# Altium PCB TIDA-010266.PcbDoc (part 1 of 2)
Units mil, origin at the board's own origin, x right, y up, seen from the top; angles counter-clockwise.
Board outline 2450.67 x 2507.13 mil, 4 copper layers (Top Layer, Signal Layer 1, Signal Layer 2, Bottom Layer), stack 61.6 mil thick; 88 components, 56 nets, 233 pads, 159 vias.
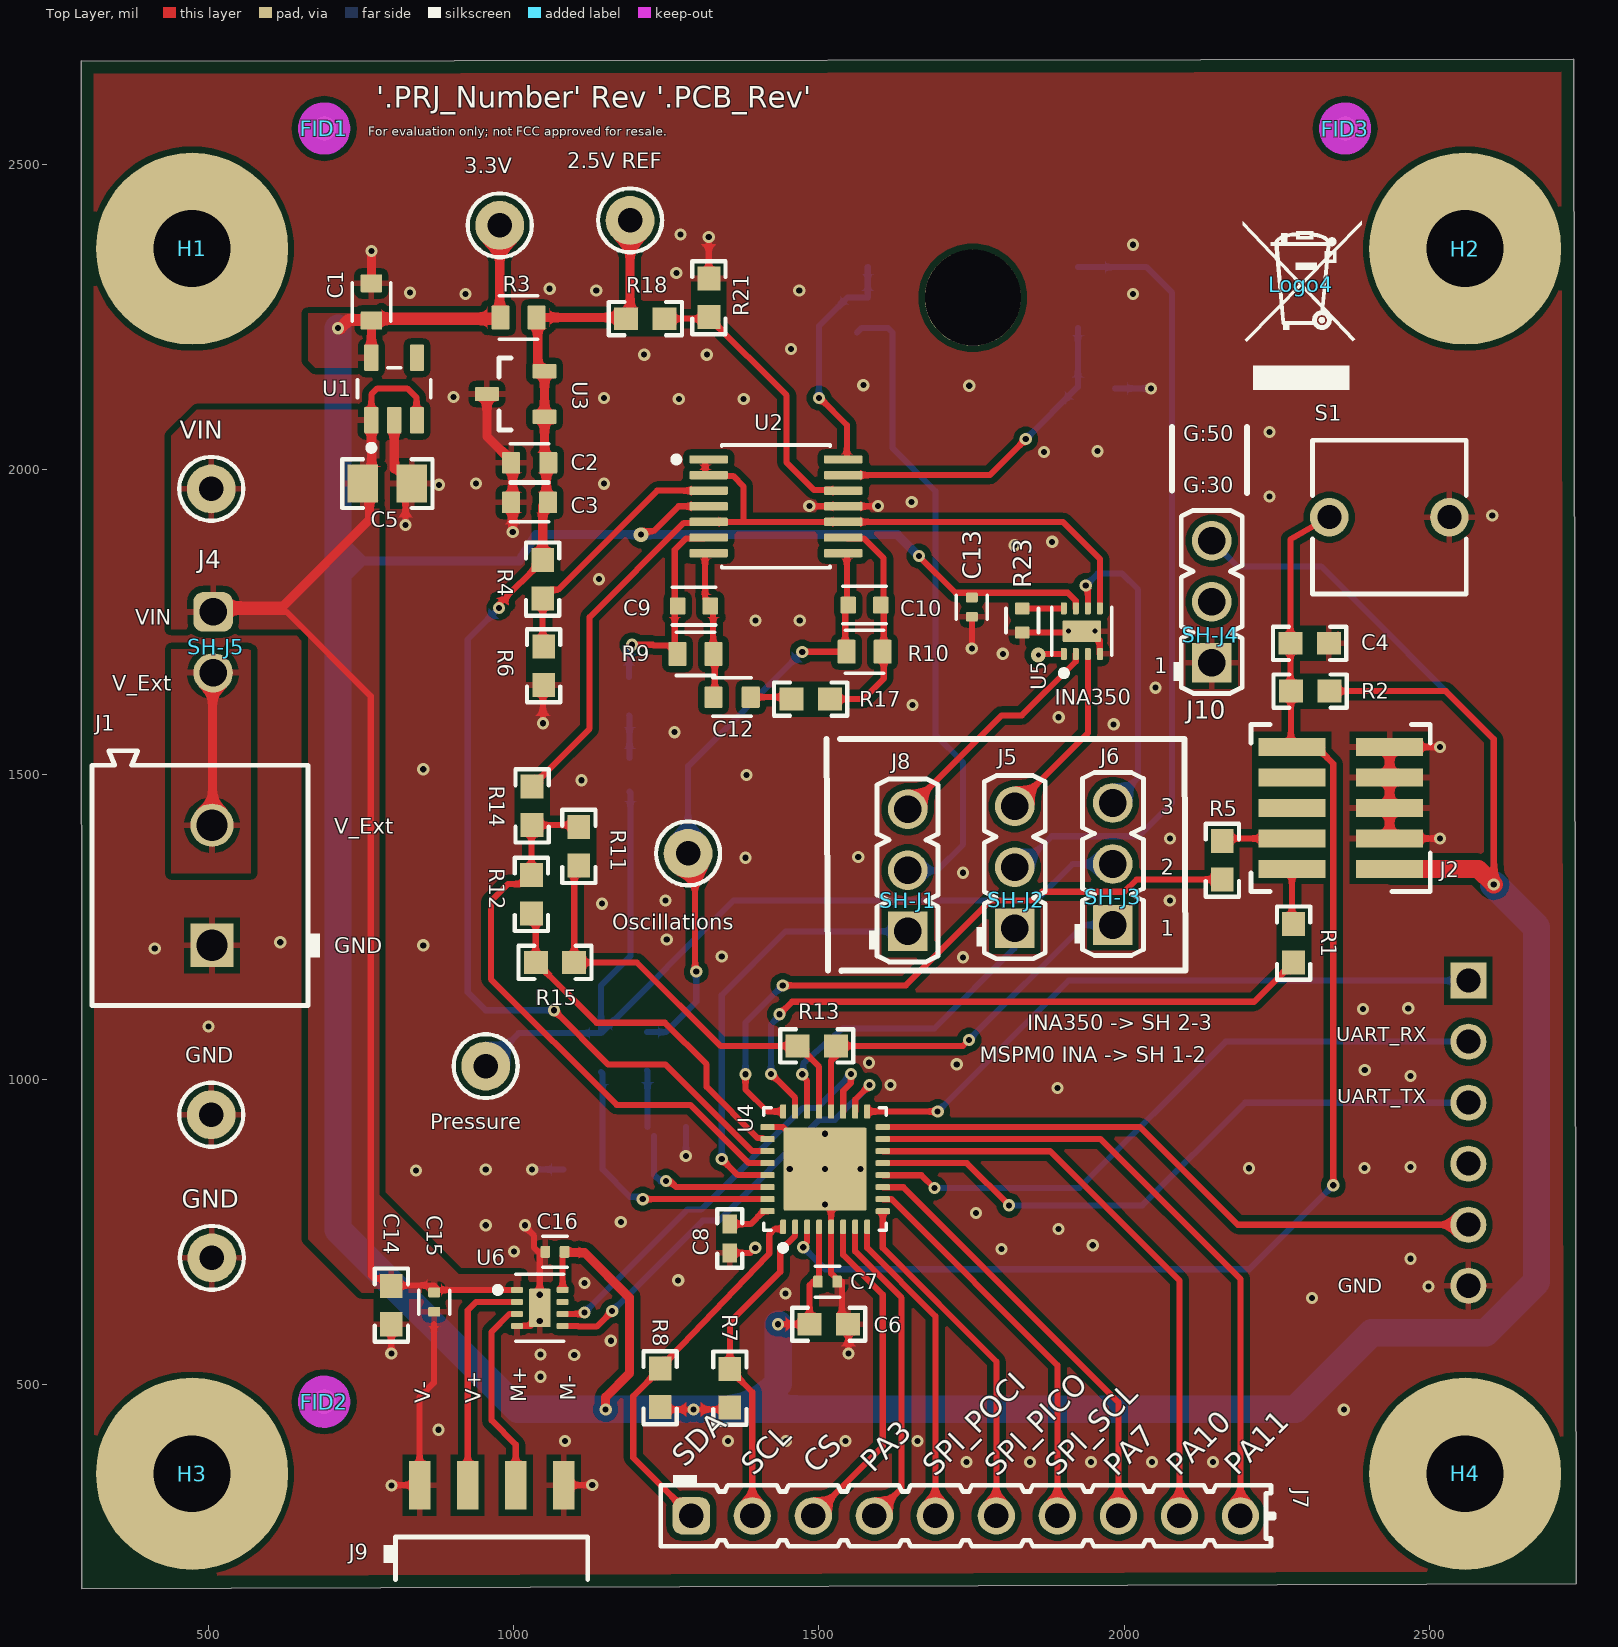
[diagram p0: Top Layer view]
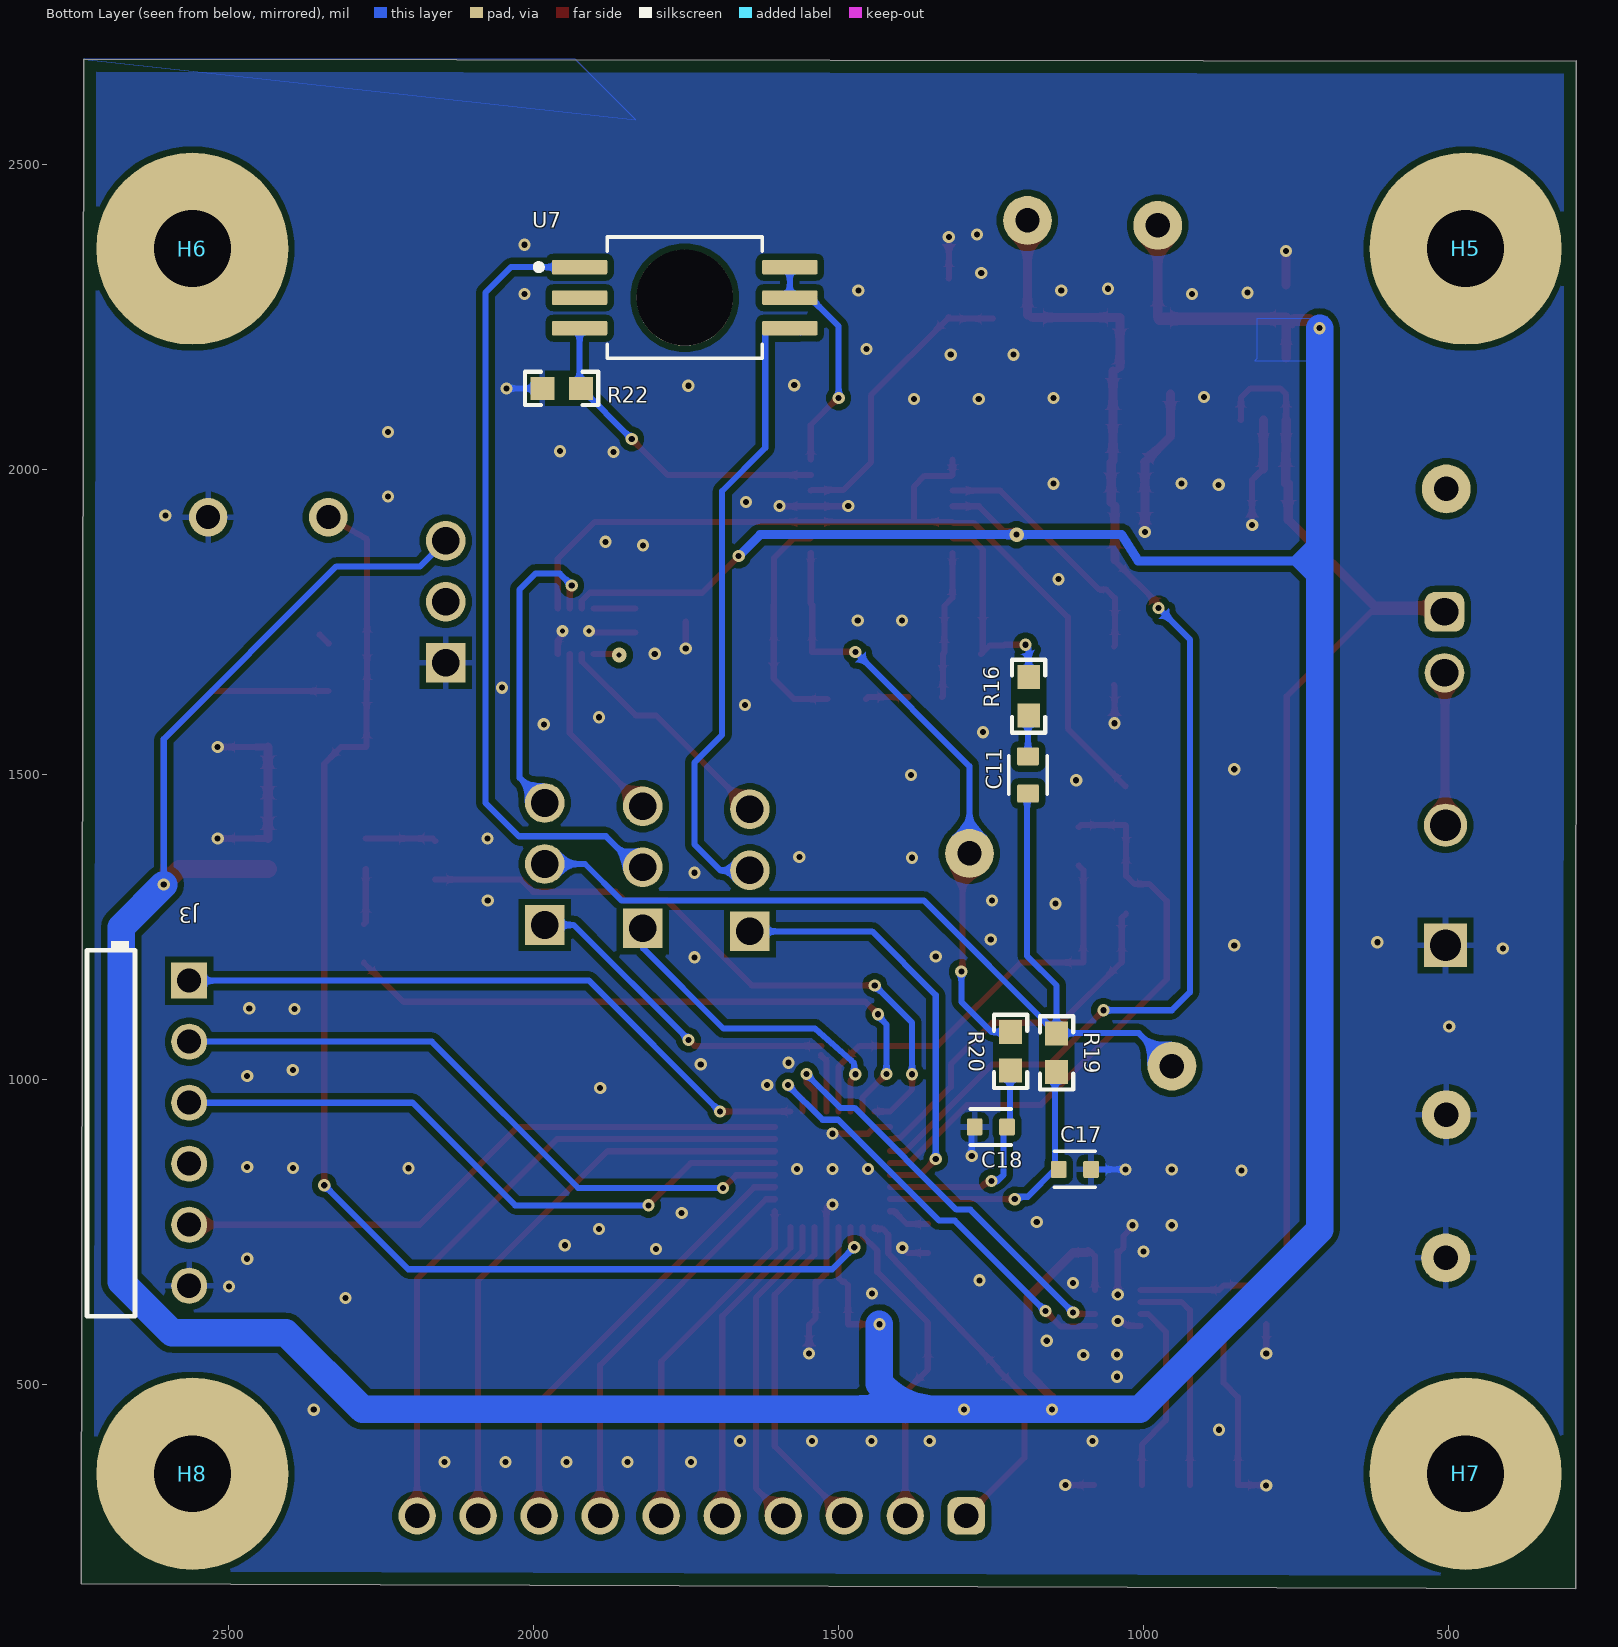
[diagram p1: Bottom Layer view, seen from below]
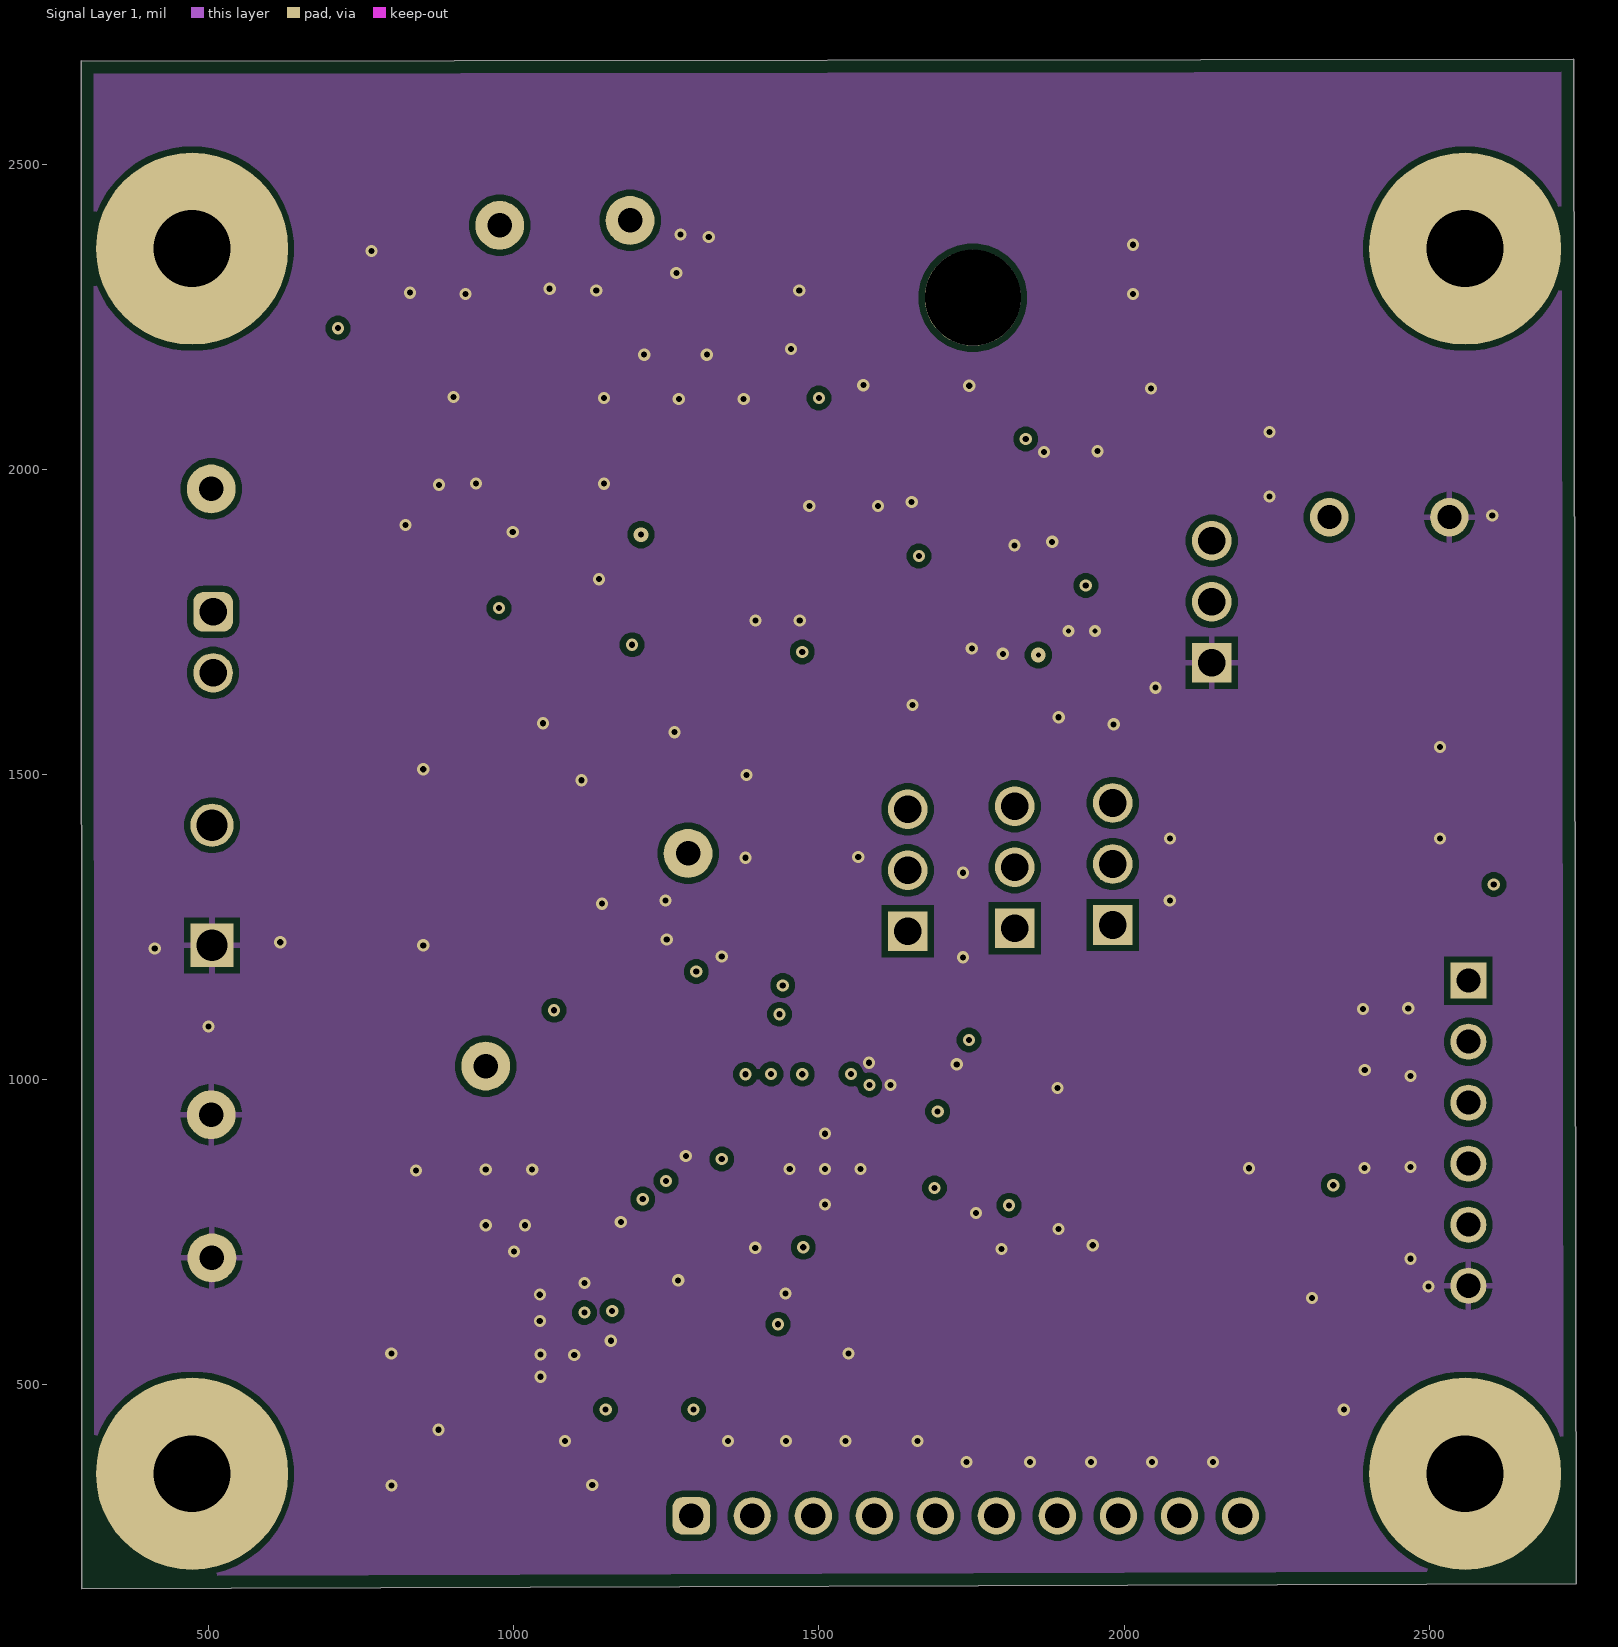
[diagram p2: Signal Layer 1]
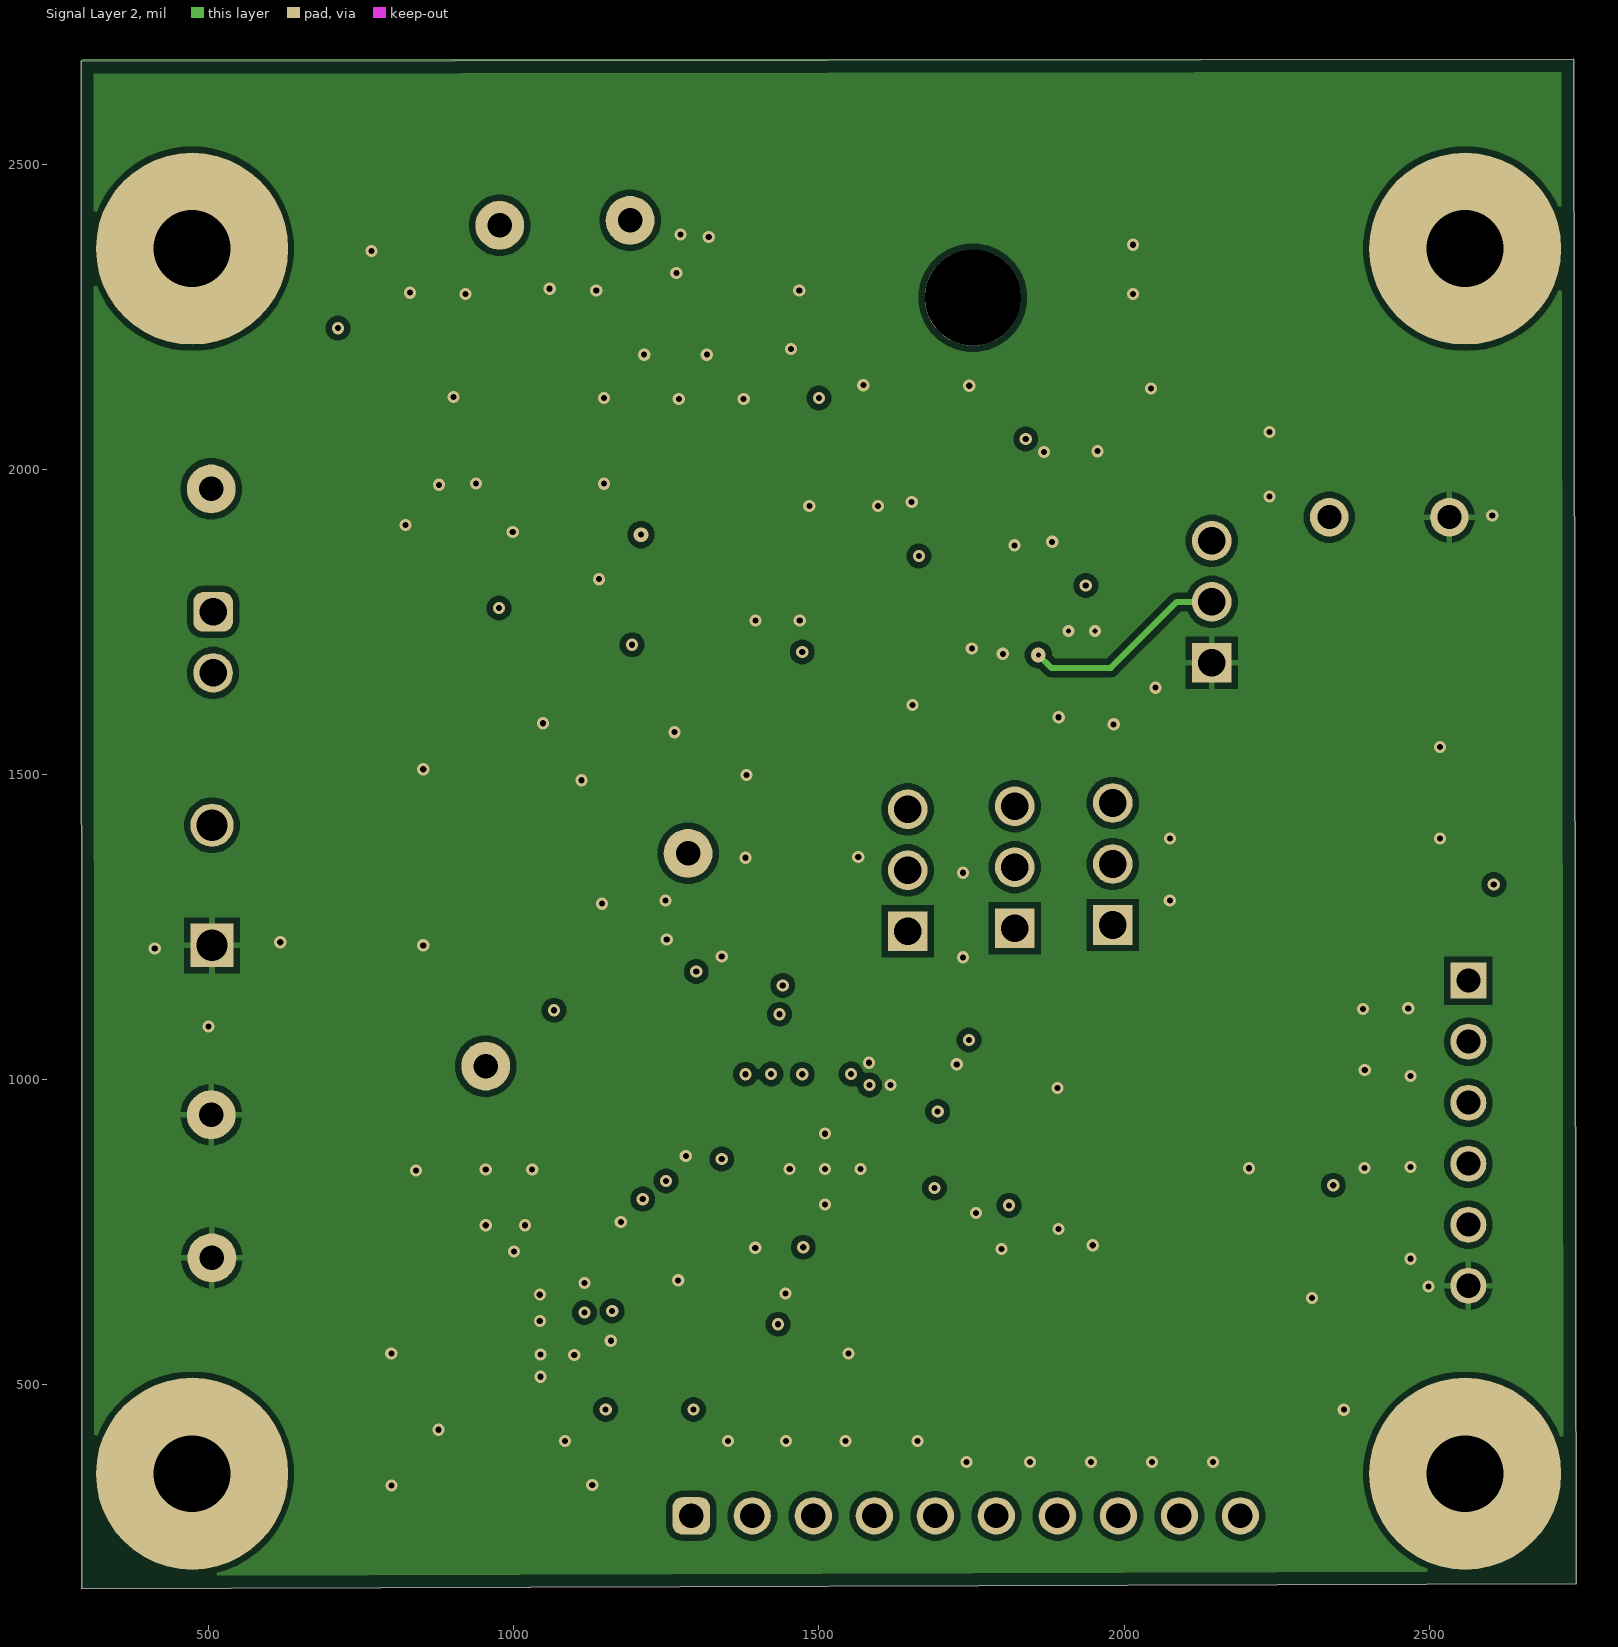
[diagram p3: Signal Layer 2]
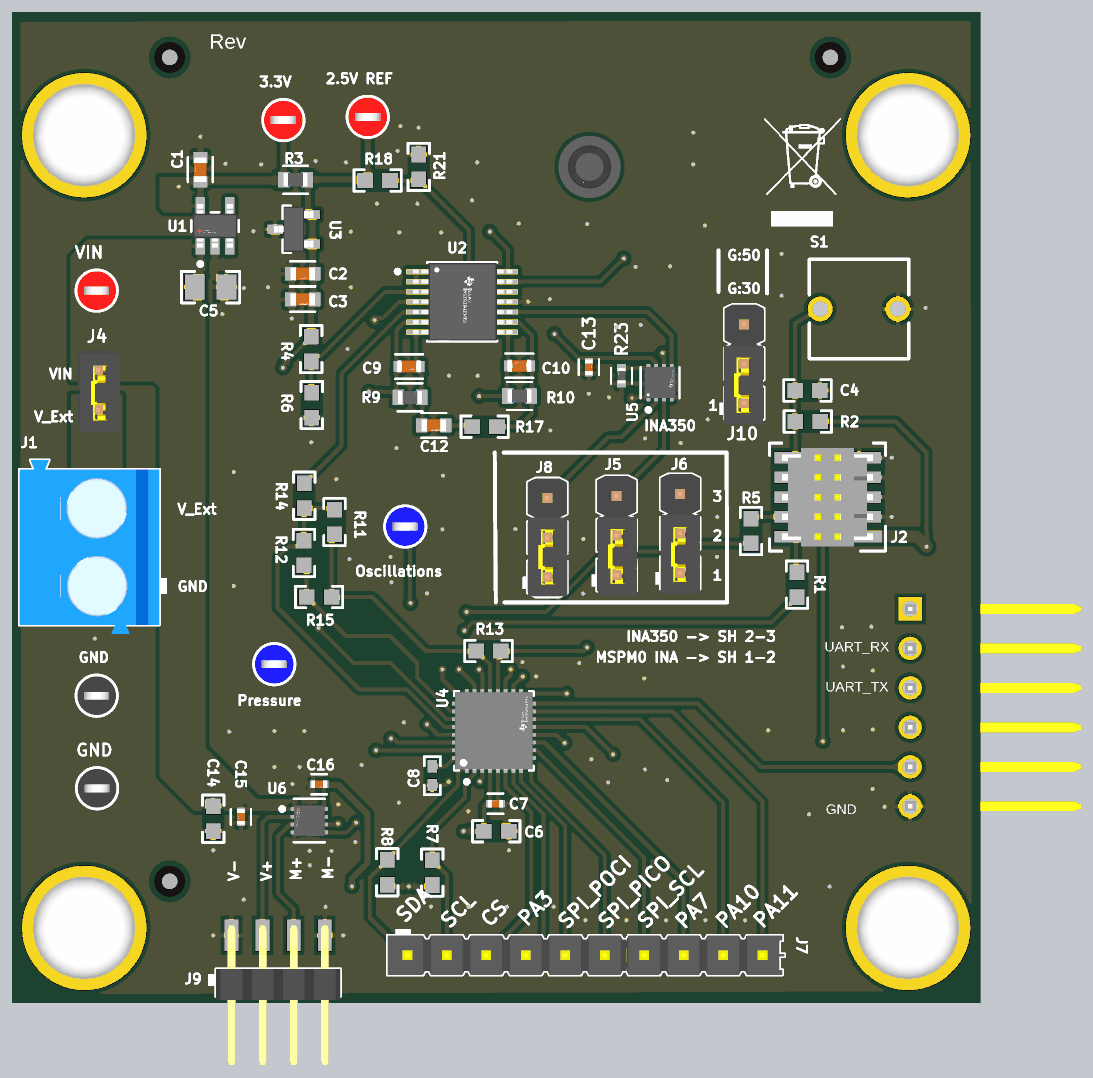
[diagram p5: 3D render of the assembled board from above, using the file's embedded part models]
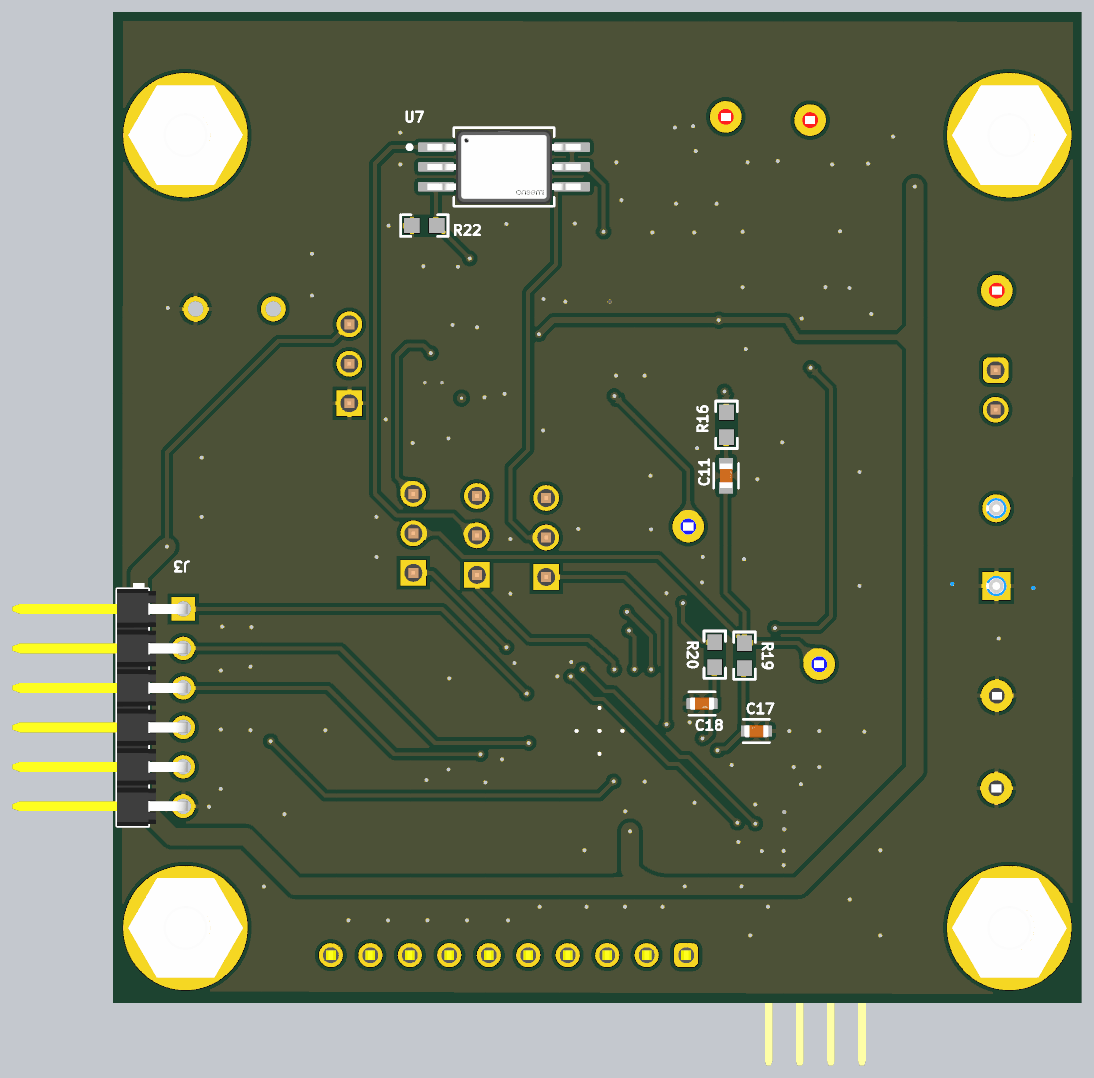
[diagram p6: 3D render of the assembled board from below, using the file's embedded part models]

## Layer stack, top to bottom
Top Solder: solder mask 0.4, Solder Resist, Dk 3.5
Top Layer: signal copper 1.4
Dielectric 1: prepreg 8, FR-4 High Tg, Dk 4.2
Signal Layer 1: signal copper 1.4
Dielectric 2: core 40, FR-4 High Tg, Dk 4.2
Signal Layer 2: signal copper 1.4
Dielectric 3: prepreg 8, FR-4 High Tg, Dk 4.2
Bottom Layer: signal copper 1.4
Bottom Solder: solder mask 0.4, Solder Resist, Dk 3.5

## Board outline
291.81,165.64 291.07,2669.88 290.71,2669.49 2737.21,2672.77 2736.86,2672.31 2741.38,173.75 2740.98,174.04

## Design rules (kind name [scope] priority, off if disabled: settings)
AcuteAngle [All] p1: minimum=4.50000000000000E+0001 checktracksonly=FALSE
AssemblyTestPointUsage [All] p1: valid=2
BoardOutlineClearance BoardOutlineClearance_MountingHoles [OnCopper and InComponentClass('Mounting Holes')] p1: gap=20 ignorepadtopadclearanceinfootprint=FALSE
BoardOutlineClearance BoardOutlineClearance_Poly [OnCopper and IsPoly] p2: gap=20 ignorepadtopadclearanceinfootprint=FALSE
BoardOutlineClearance [OnCopper and Not InComponentClass('Logo') and not InComponentClass('FiducialMark') and not InRegion(1000,500,4000,800) and not InPoly] p3: gap=20 ignorepadtopadclearanceinfootprint=FALSE
Clearance Clearance_Keepouts [((IsTrack Or IsArc) And Not InPoly) And IsFree and IsKeepOut vs ((IsTrack Or IsArc) And Not InPoly) And IsFree and IsKeepOut] p1: gap=0 ignorepadtopadclearanceinfootprint=FALSE
Clearance Clearance_Poly [InPolygon] p2: gap=10 ignorepadtopadclearanceinfootprint=TRUE
Clearance Clearance_FiducialMark [IsKeepOut and InComponentClass('FiducialMark') vs IsPad and InComponentClass('FiducialMark')] p3: gap=0 ignorepadtopadclearanceinfootprint=FALSE
Clearance [All] p4: gap=8 ignorepadtopadclearanceinfootprint=TRUE
ComponentClearance ComponentClearance_MountingHoles_FiducialMarks [InComponentClass('Mounting Holes') vs InComponentClass('FiducialMark')] p1: gap=10 collisioncheckmode=3 verticalgap=10 showdistances=FALSE
ComponentClearance ComponentClearance_Shunt [InComponentClass('Header') vs InComponentClass('Shunt')] p2: gap=0 collisioncheckmode=3 verticalgap=0 showdistances=FALSE
ComponentClearance ComponentClearance_Logo [InComponentClass('Logo')] p3: gap=10 collisioncheckmode=3 verticalgap=10 showdistances=FALSE
ComponentClearance ComponentClearance_ScrewToNut [(HasFootprint('NY PMS 440 0025 PH')) vs (HasFootprint('Keystone_1902C'))] p4: gap=5 collisioncheckmode=3 verticalgap=10 showdistances=FALSE
ComponentClearance ComponentClearance_MountingHoles [InComponentClass('Mounting Holes')] p5: gap=10 collisioncheckmode=3 verticalgap=100000 showdistances=FALSE
ComponentClearance ComponentClearance_SmallPassives [HasFootprint('0201*') or HasFootprint('0402*') or HasFootprint('0508') or HasFootprint('0603*') or HasFootprint('0612') or HasFootprint('0805*') or HasFootprint('0815*') or HasFootprint('0830*') or HasFootprint('1206*') or HasFootprint('1210*') or HasFootprint('1808*') or HasFootprint('1812*') or HasFootprint('1825*') or HasFootprint('2010*') or HasFootprint('2220*') or HasFootprint('2225*') or HasFootprint('2512*') or HasFootprint('2728*') or HasFootprint('3518*') vs HasFootprint('0201*') or HasFootprint('0402*') or HasFootprint('0508') or HasFootprint('0603*') or HasFootprint('0612') or HasFootprint('0805*') or HasFootprint('0815*') or HasFootprint('0830*') or HasFootprint('1206*') or HasFootprint('1210*') or HasFootprint('1808*') or HasFootprint('1812*') or HasFootprint('1825*') or HasFootprint('2010*') or HasFootprint('2220*') or HasFootprint('2225*') or HasFootprint('2512*') or HasFootprint('2728*') or HasFootprint('3518*')] p6: gap=10 collisioncheckmode=3 verticalgap=10 showdistances=FALSE
ComponentClearance ComponentClearance_THtoSMT [IsThruComponent vs IsSMTComponent] p7: gap=10 collisioncheckmode=3 verticalgap=30 showdistances=FALSE
ComponentClearance ComponentClearance_THtoTH [IsThruComponent vs IsThruComponent] p8: gap=10 collisioncheckmode=3 verticalgap=30 showdistances=FALSE
ComponentClearance [All] p9: gap=10 collisioncheckmode=3 verticalgap=10 showdistances=FALSE
DiffPairsRouting [All] p1: maxlimit=100 minlimit=10 mostfreqgap=10 toplayer_minwidth=15 toplayer_maxwidth=15 toplayer_prefwidth=15 midlayer1_minwidth=15 midlayer1_maxwidth=15 midlayer1_prefwidth=15 midlayer2_minwidth=15 midlayer2_maxwidth=15 midlayer2_prefwidth=15 bottomlayer_minwidth=15 bottomlayer_maxwidth=15 bottomlayer_prefwidth=15 maxuncoupledlength=1000
FabricationTestPointUsage TestPointUsage [All] p1: valid=2 allowmultiple=FALSE
FabricationTestpoint Testpoint [All] p1: side=3 testpointundercomponent=TRUE minsize=40 maxsize=100 preferedsize=60 minholesize=0 maxholesize=40 preferedholesize=32 testpointgrid=1 allowsidetop=TRUE allowsidebottom=TRUE usegrid=TRUE gridtolerance=0.01
FanoutControl Fanout_LCC [IsLCC] p1: bgadir=Out bgaviamode=Centered fanoutstyle=Auto fanoutdirection=Alternating viagrid=1 // Fanout_LCC (Default Rule)
FanoutControl Fanout_BGA [IsBGA] p2: bgadir=Out bgaviamode=Centered fanoutstyle=Auto fanoutdirection=Alternating viagrid=1 // Fanout_BGA (Default Rule)
FanoutControl Fanout_Default [All] p4: bgadir=Out bgaviamode=Centered fanoutstyle=Auto fanoutdirection=Alternating viagrid=1 // Fanout_Default (Default Rule)
FanoutControl Fanout_Small [(CompPinCount < 5)] p5: bgadir=Out bgaviamode=Centered fanoutstyle=Auto fanoutdirection=OutThenIn viagrid=1 // Fanout_Small (Default Rule)
HoleSize [All] p1: absolutevalues=TRUE maxlimit=251 minlimit=6 maxpercent=80.000 minpercent=20.000
MinimumAnnularRing MinimumAnnularRing_ThermalPadVias [IsVia and InAnyComponent] p1: minimumring=5.91
MinimumAnnularRing [All] p2: minimumring=7.87
MinimumSolderMaskSliver MinimumSolderMaskSliver_Logo [InComponentClass('Logo') vs InComponentClass('Logo')] p1: minsoldermaskwidth=0.7
MinimumSolderMaskSliver [All] p2: minsoldermaskwidth=3.94
PlaneConnect [All] p1: planeconnectstyle=Relief reliefexpansion=10 reliefentries=4 reliefconductorwidth=10 reliefairgap=10
PolygonConnect [All] p1: thpad.connectstyle=Relief thpad.reliefconductorwidth=10 thpad.reliefentries=4 thpad.polygonreliefangle="90 Angle" thpad.airgapwidth=10 smdpad.connectstyle=Relief smdpad.reliefconductorwidth=10 smdpad.reliefentries=4 smdpad.polygonreliefangle="90 Angle" smdpad.airgapwidth=10 via.connectstyle=Direct via.reliefconductorwidth=10 via.reliefentries=4 via.polygonreliefangle="90 Angle" via.airgapwidth=10
RoutingLayers [All] p1: top layer_v5=TRUE mid layer 1_v5=FALSE mid layer 2_v5=FALSE bottom layer_v5=TRUE
RoutingVias ThermalPadVias [IsVia and InAnyComponent] p1: holewidth=7.87 width=19.68 viastyle="Through Hole" minholewidth=7.87 minwidth=19.68 maxholewidth=12.99 maxwidth=23.62
RoutingVias [All] p2: holewidth=10 width=10 viastyle="Through Hole" minholewidth=7.87 minwidth=20 maxholewidth=40 maxwidth=65
SilkToBoardRegionClearance [Not ((IsComment or IsDesignator) And (Hide <> 'False')) and not InRegion(1000,500,4000,800)] p1:
SilkToSilkClearance SilkToSilkClearance_Pb-FreeLogo [(HasFootprint('Pb-Free_Overlay_Medium') OR HasFootprint('Pb-Free_Overlay_Small')) vs (HasFootprint('Pb-Free_Overlay_Medium') OR HasFootprint('Pb-Free_Overlay_Small'))] p1: silktosilkclearance=0
SilkToSilkClearance [All] p2: silktosilkclearance=3.94
SilkToSolderMaskClearance SilkToComponentPadClearance [(IsPad or IsFill or IsRegion) and InAnycomponent] p1: minsilkscreentomaskgap=5 clearancetoexposedcopper=TRUE
SilkToSolderMaskClearance "Silk to Solder Mask Opening" [All] p2: minsilkscreentomaskgap=3.94 clearancetoexposedcopper=FALSE
SolderMaskExpansion [All] p1: expansion=1.97 istentingtop=FALSE
UnRoutedNet [All] p1: checkbadconnections=TRUE
Width [All] p1: maxlimit=100 minlimit=6 preferedwidth=10 checkconnectedcopper=TRUE
13 further rules are at their usual default settings.

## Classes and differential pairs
component class Shunt: SH-J1 SH-J2 SH-J3 SH-J4 SH-J5
component class TIDA-010266_BPM: C1 C2 C3 C4 C5 C6 C7 C8 C9 C10 C11 C12 C13 C14 C15 C16 C17 C18 J1 J2 J3 J4 J5 J6 J7 J8 J9 J10 R1 R2 R3 R4 R5 R6 R7 R8 R9 R10 R11 R12 R13 R14 R15 R16 R17 R18 R19 R20 R21 R22 R23 S1 TP1 TP2 TP3 TP4 TP5 TP6 U1 U2 U3 U4 U5 U6 U7
component class Header: J3 J4 J5 J6 J7 J8 J9 J10
component class AssemblyNote: ZZ1 ZZ2 ZZ3 ZZ4
component class FiducialMark: FID1 FID2 FID3
component class TIDA-010266_Hardware: FID1 FID2 FID3 H1 H2 H3 H4 H5 H6 H7 H8 Logo3 Logo4 SH-J1 SH-J2 SH-J3 SH-J4 SH-J5 ZZ1 ZZ2 ZZ3 ZZ4
component class "Mounting Holes": H1 H2 H3 H4

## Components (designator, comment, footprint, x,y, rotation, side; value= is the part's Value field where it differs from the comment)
"2.5V REF" "5000" Keystone5000 1190.4,2408.56 r90 top (schematic designator TP4)
3.3V "5000" Keystone5000 976.76,2400.4 r90 top (schematic designator TP3)
C1 "GRM188R61C475KE11D" FP-GRM188R61C475KE11D_0603-MFG 766.49,2274.82 r270 top value=4.7µF
C2 "GRM188R61C475KE11D" FP-GRM188R61C475KE11D_0603-MFG 1025.89,2011.23 r0 top value=4.7µF
C3 "GRM188R61C475KE11D" FP-GRM188R61C475KE11D_0603-MFG 1025.59,1946.25 r0 top value=4.7µF
C4 "GRM1885C1H112JA01D" 0603 2304.16,1715.31 r0 top value=1100pF
C5 "GCM21BR71H105KA03K" 0805_HV 792.58,1977.24 r0 top value=1uF
C6 "GRM188R61A106ME69D" 0603 1516.04,599.3 r0 top value=10uF
C7 "GRM155R71E104KE14J" FP-GRM155R71E104KE14J_0402-MFG 1513.95,669.03 r180 top value=100nF
C8 "GRM155C80J474KE19D" 0402 1353.83,739.94 r270 top value=0.47uF
C9 "GCJ188R71E104KA12D" FP-GCJ188R71E104KA12D_0603-MFG 1295.12,1776.5 r0 top value=100nF
C10 "GCJ188R71E104KA12D" FP-GCJ188R71E104KA12D_0603-MFG 1574.55,1777.91 r180 top value=100nF
C11 "GRM188R61C475KE11D" FP-GRM188R61C475KE11D_0603-MFG 1189.5,1499.58 r90 bottom value=4.7µF
C12 "GRM188R61C475KE11D" FP-GRM188R61C475KE11D_0603-MFG 1357.67,1627.1 r0 top value=4.7µF
C13 "GRM155R71E104KE14J" FP-GRM155R71E104KE14J_0402-MFG 1750.51,1774.65 r90 top value=100nF
C14 "CL10A226MO7JZNC" 0603 799.08,630.8 r270 top value=22uF
C15 "GRM155R71E104KE14J" FP-GRM155R71E104KE14J_0402-MFG 869.39,635.62 r270 top value=100nF
C16 "GRM155R71E104KE14J" FP-GRM155R71E104KE14J_0402-MFG 1067.24,718.12 r0 top value=100nF
C17 "GCM1885C2A101JA16J" FP-GCM1885C2A101JA16J_0603-MFG 1112.76,853.05 r0 bottom value=100pF
C18 "GCM1885C2A101JA16J" FP-GCM1885C2A101JA16J_0603-MFG 1250.52,922.62 r180 bottom value=100pF
FID1 "Fiducial" Fiducial10-20 688.98,2559.06 r0 top
FID2 "Fiducial" Fiducial10-20 688.98,472.44 r0 top
FID3 "Fiducial" Fiducial10-20 2362.2,2559.06 r0 top
GND "5001" Keystone5001 505,708.12 r90 top (schematic designator TP7)
GND "5001" Keystone5001 503.94,942.64 r90 top (schematic designator TP6)
H1 "NY PMS 440 0025 PH" "NY PMS 440 0025 PH" 472.44,2362.2 r0 top
H2 "NY PMS 440 0025 PH" "NY PMS 440 0025 PH" 2559.06,2362.2 r0 top
H3 "NY PMS 440 0025 PH" "NY PMS 440 0025 PH" 472.44,354.33 r0 top
H4 "NY PMS 440 0025 PH" "NY PMS 440 0025 PH" 2559.06,354.33 r0 top
H5 "1902C" Keystone_1902C 472.44,2362.2 r180 bottom
H6 "1902C" Keystone_1902C 2559.06,2362.2 r180 bottom
H7 "1902C" Keystone_1902C 472.44,354.33 r180 bottom
H8 "1902C" Keystone_1902C 2559.06,354.33 r180 bottom
J1 "CMP-0054828-1" Wurth_691101710002 505.24,1318.77 r90 top
J2 "FTSH-105-01-L-DV-K" Samtec_FTSH-105-01-x-DV-K 2355.12,1445.46 r180 top
J3 "90121-0766" Molex_90121-0766 2564.32,912.41 r270 bottom
J4 "61300211121" WURTH_61300211121 506.93,1716.85 r270 top
J5 "61300311121" WURTH_61300311121 1820.76,1348.45 r90 top
J6 "61300311121" WURTH_61300311121 1981.66,1353.67 r90 top
J7 "TSW-110-08-G-S" Samtec_TSW-110-08-x-S 1740.68,285.31 r0 top
J8 "61300311121" WURTH_61300311121 1645.27,1343.17 r90 top
J9 "M22-5330405" Harwin_M22-5330405 963.63,335.62 r0 top
J10 "61300311121" WURTH_61300311121 2143.79,1783.24 r90 top
Logo3 "FCC disclaimer" FCC_disclaimer 2370,3350 r0 top
Logo4 "WEEE logo" WEEE_Minimum 2290.21,2303.37 r0 top
Oscillations "5117" Keystone5117 1285.45,1370.99 r90 top (schematic designator TP5)
Pressure "5117" Keystone5117 953.74,1022.32 r90 top (schematic designator TP2)
R1 "CRCW060327R0JNEA" 0603 2277.77,1223.9 r270 top value=27
R2 "CRCW060347K0FKEA" 0603 2304.95,1636.93 r0 top value=47.0k
R3 "CRCW0603330RFKEA" FP-CRCW0603330RFKEA_0603-MFG 1007.47,2249.41 r180 top value=330
R4 "CRCW060310K0FKEA" 0603 1047.16,1820.47 r90 top value=10.0k
R5 "CRCW060327R0JNEA" 0603 2160.96,1359.76 r270 top value=27
R6 "CRCW060310K0FKEA" 0603 1048.83,1678.53 r90 top value=10.0k
R7 "CRCW060310K0FKEA" 0603 1353.89,494.56 r270 top value=10.0k
R8 "CRCW060310K0FKEA" 0603 1239.76,495.26 r270 top value=10.0k
R9 "CRCW0603270KFKEA" FP-CRCW0603270KFKEA_0603-MFG 1297.65,1698.08 r0 top value=270k
R10 "CRCW0603270KFKEA" FP-CRCW0603270KFKEA_0603-MFG 1574.73,1701.54 r180 top value=270k
R11 "CRCW060320K0FKEA" 0603 1106.33,1382.55 r270 top value=20.0k
R12 "CRCW0603499RFKEAC" 0603 1028.69,1303.95 r270 top value=499
R13 "CRCW060320K0FKEA" 0603 1496.34,1055.47 r0 top value=20.0k
R14 "CRCW060320K0FKEA" 0603 1029.89,1448.9 r270 top value=20.0k
R15 "CRCW0603499RFKEAC" 0603 1067.35,1192.21 r0 top value=499
R16 "CRCW060320K0FKEA" 0603 1188.41,1628.63 r90 bottom value=20.0k
R17 "CRCW060320K0FKEA" 0603 1486.34,1623.92 r0 top value=20.0k
R18 "CRCW060345K3FKEA" 0603 1215.34,2247.38 r180 top value=45.3k
R19 "CRCW0603200RFKEA" 0603 1142.79,1043.98 r270 bottom value=200
R20 "CRCW0603200RFKEA" 0603 1218.1,1046.52 r270 bottom value=200
R21 "CRCW06034K99FKEAC" 0603 1319.56,2281.73 r270 top value=4.99k
R22 "RT0603BRD072K49L" 0603 1953.83,2133.1 r180 bottom value=2.49k
R23 "RC0402FR-070RL" FP-RC0402FR-070RL_0402-MFG 1833.17,1752.73 r90 top value=0
S1 "EVQ-21505R" SW_EVQ-21x05 2434.75,1922.02 r0 top
SH-J1 "Place SH-J1 on J8 pins 1-2" SNT-100-BK-G 1646.38,1293.93 r90 top value=1x2
SH-J2 "Place SH-J2 on J5 pins 1-2" SNT-100-BK-G 1823,1295 r90 top value=1x2
SH-J3 "Place SH-J3 on J6 pins 1-2" SNT-100-BK-G 1982,1300 r90 top value=1x2
SH-J4 "Place SH-J4 on J10 pins 1-2" SNT-100-BK-G 2142,1729 r90 top value=1x2
SH-J5 "Place SH-J5 on J4 pins 1-2" SNT-100-BK-G 512.52,1709.33 r90 top value=1x2
U1 "TPS7A2433DBVR" DBV0005A-MFG 803.77,2132.26 r90 top
U2 "LMV324AIPWR" PW0014A-MFG 1429.45,1939.91 r0 top
U3 "ATL431LIBIDBZR" DBZ0003A_N 1003.01,2123.9 r180 top
U4 "MSPM0L1306SRHB" RHB0032N-MFG 1510.1,853.48 r90 top
U5 "INA350CDSIDSGR" DSG0008A-MFG 1930.78,1735.32 r90 top
U6 "DRV8210DSGR" DSG0008A-MFG 1042.42,626.04 r0 top
U7 "2SMPP03" FP-2SMPP03_SMD6-MFG 1752.13,2281.83 r180 bottom
VIN "5000" Keystone5000 503.94,1968.5 r90 top (schematic designator TP1)
ZZ1 "This Assembly Note is for PCB labels only" AssemblyNoteLabel 185,3938 r0 top
ZZ2 "These assemblies are ESD sensitive, ESD precautions shall be observed." AssemblyNote 185,3829.11 r0 top
ZZ3 "These assemblies must be clean and free from flux and all contaminants. Use of no clean flux is not acceptable." AssemblyNote 185,3740.56 r0 top
ZZ4 "These assemblies must comply with workmanship standards IPC-A-610 Class 2, unless otherwise specified." AssemblyNote 185,3652 r0 top

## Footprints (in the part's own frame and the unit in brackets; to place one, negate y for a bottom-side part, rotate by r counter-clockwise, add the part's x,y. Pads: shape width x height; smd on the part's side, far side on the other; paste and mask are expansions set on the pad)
0402 [mm] "0402 from SM-752 data"
  rect 0.8x0.6 smd: 1(-0.6,0) 2(0.6,0)
  silkscreen extent -1.22,-0.52 1.22,0.52, body extent -0.55,-0.3 0.55,0.3, height 0.6
0603 [mm] "0603 from SM-752 data"
  rect 1x0.95 smd: 1(-0.8,0) 2(0.8,0)
  silkscreen extent -1.52,-0.69 1.52,0.69, body extent -0.87,-0.47 0.87,0.47, height 1
0805_HV [mil] "0805 with 30mil clearance between pads"
  rect 50x63 smd: 1(-40,0) 2(40,0)
  silkscreen extent -74,-40 74,40, body extent -43,-29 43,29, height 57
AssemblyNote [mil] "Assembly Note"
AssemblyNoteLabel [mil] "Assembly Note for PCB Labels"
DBV0005A-MFG [mm]
  rrect17% 1.1x0.6 smd paste+0 mask+0: 1(-1.3,0.95) 2(-1.3,0) 3(-1.3,-0.95) 4(1.3,-0.95) 5(1.3,0.95)
  silkscreen extent -2.57,-1.53 0.87,1.53, body extent -1.95,-1.78 1.95,1.78, height 0.25
DBZ0003A_N [mm] "SOT23, 3-Leads, Body 2.9x1.3mm, Pitch 0.95mm, Lead Span 2.4mm, IPC Medium Density"
  rrect17% 1x0.6 smd: 1(-1.2,0.95) 2(-1.2,-0.95) 3(1.2,0)
  silkscreen extent 0.2,-1.5 0.7,1.5, body extent -1.26,-1.46 1.26,1.46, height 0.98
DSG0008A-MFG [mm]
  rrect40% 0.5x0.25 smd paste+0 mask+0: 1(-0.95,0.75) 2(-0.95,0.25) 3(-0.95,-0.25) 4(-0.95,-0.75) 5(0.95,-0.75) 6(0.95,-0.25) 7(0.95,0.25) 8(0.95,0.75)
  rrect11% 0.9x1.6 smd paste-1000 mask+0: 9(0,0)
  silkscreen extent -1.87,-1.25 1,1.25, body extent -1.3,-1.15 1.3,1.15, height 0.25
FCC_disclaimer [mil]
Fiducial10-20 [mm]
  round 1 smd mask+0.5: 1(0,0)
  Top Layer keep-out circle w1.178: c0,0 r0.5
FP-2SMPP03_SMD6-MFG [mm]
  rrect17% 2.3x0.6 smd paste+0 mask+0: 1(-4.375,1.27) 2(-4.375,0) 3(-4.375,-1.27) 4(4.375,-1.27) 5(4.375,0) 6(4.375,1.27)
  round 4 hole 4 unplated paste-1000 mask+0: ""(0,0)
  silkscreen extent -6.2,-2.52 3.22,2.52, body extent -4.92,-2.37 4.92,2.37, height 2
FP-CRCW0603270KFKEA_0603-MFG [mm]
  rrect13% 0.75x1 smd paste+0 mask+0: 1(-0.75,0) 2(0.75,0)
  silkscreen extent -0.8,-0.9 0.8,0.9, body extent -1.22,-0.6 1.22,0.6, height 0.25
FP-CRCW0603330RFKEA_0603-MFG [mm]
  rrect13% 0.75x1 smd paste+0 mask+0: 1(-0.75,0) 2(0.75,0)
  silkscreen extent -0.8,-0.9 0.8,0.9, body extent -1.22,-0.6 1.22,0.6, height 0.25
FP-GCJ188R71E104KA12D_0603-MFG [mm]
  rrect15% 0.65x0.7 smd paste+0 mask+0: 1(-0.675,0) 2(0.675,0)
  silkscreen extent -0.9,-0.79 0.9,0.77, body extent -1.1,-0.55 1.1,0.55, height 0.25
FP-GCM1885C2A101JA16J_0603-MFG [mm]
  rrect15% 0.65x0.7 smd paste+0 mask+0: 1(-0.675,0) 2(0.675,0)
  silkscreen extent -0.85,-0.75 0.85,0.75, body extent -0.8,-0.4 0.8,0.4, height 0.9
FP-GRM155R71E104KE14J_0402-MFG [mm]
  rrect25% 0.4x0.5 smd paste+0 mask+0: 1(-0.4,0) 2(0.4,0)
  silkscreen extent -0.5,-0.65 0.5,0.65, body extent -0.7,-0.38 0.7,0.38, height 0.25
FP-GRM188R61C475KE11D_0603-MFG [mm]
  rrect13% 0.75x0.9 smd paste+0 mask+0: 1(-0.775,0) 2(0.775,0)
  silkscreen extent -0.8,-0.8 0.8,0.8, body extent -1.25,-0.58 1.25,0.58, height 0.25
FP-RC0402FR-070RL_0402-MFG [mm]
  rrect20% 0.5x0.6 smd paste+0 mask+0: 1(-0.5,0) 2(0.5,0)
  silkscreen extent -0.5,-0.67 0.5,0.67, body extent -0.85,-0.4 0.85,0.4, height 0.25
Harwin_M22-5330405 [mm] "Header, 2mm, 4x1, R/A, SMT"
  rect 0.89x2.03 smd: 1(-3,0) 2(-1,0) 3(1,0) 4(3,0)
  silkscreen extent -4.5,-3.93 4,-2.17, body extent -4,-8.36 4,0.64, height 2
Keystone5000 [mil] "For Keystone 500x miniature loop terminals"
  round 80 hole 40: 1(0,0)
  silkscreen extent -52,-52 52,52, body extent -49,-49 49,49, height 182
Keystone5001 [mil] "For Keystone 500x miniature loop terminals"
  round 80 hole 40: 1(0,0)
  silkscreen extent -52,-52 52,52, body extent -49,-49 49,49, height 182
Keystone5117 [mil] "For Keystone 500x miniature loop terminals"
  round 80 hole 40: 1(0,0)
  silkscreen extent -52,-52 52,52, body extent -49,-49 49,49, height 182
Keystone_1902C [mil] "Hex Standoff, 4-40 threaded, nylon"
  round 1 on Mech4: 0(0,0)
  body extent -145,-126 146,126, height 501
Molex_90121-0766 [mm] "Header, 2.54mm, 6x1, R/A, TH"
  rect 1.5x1.5 hole 1: 1(-6.35,0)
  round 1.5 hole 1: 2(-3.81,0) 3(-1.27,0) 4(1.27,0) 5(3.81,0) 6(6.35,0)
  silkscreen extent -8,-4.25 7.62,-2.25, body extent -7.62,-11 7.62,0.32, height 3.63
"NY PMS 440 0025 PH" [mm] "4-40 nylon screw and mounting hole"
  round 8 hole 3.2: 1(0,0)
  body extent -3.3,-3.3 3.3,3.3, height 2.69
PW0014A-MFG [mm]
  rrect29% 1.6x0.35 smd paste-1000 mask+0: 1(-2.8,1.95) 2(-2.8,1.3) 3(-2.8,0.65) 4(-2.8,0) 5(-2.8,-0.65) 6(-2.8,-1.3) 7(-2.8,-1.95) 8(2.8,-1.95) 9(2.8,-1.3) 10(2.8,-0.65) 11(2.8,0) 12(2.8,0.65) 13(2.8,1.3) 14(2.8,1.95)
  silkscreen extent -4.27,-2.55 2.25,2.55, body extent -3.7,-2.8 3.7,2.8, height 0.25
RHB0032N-MFG [mm]
  rrect40% 0.6x0.25 smd paste+0 mask+0: 1(-2.4,1.75) 2(-2.4,1.25) 3(-2.4,0.75) 4(-2.4,0.25) 5(-2.4,-0.25) 6(-2.4,-0.75) 7(-2.4,-1.25) 8(-2.4,-1.75) 17(2.4,-1.75) 18(2.4,-1.25) 19(2.4,-0.75) 20(2.4,-0.25) 21(2.4,0.25) 22(2.4,0.75) 23(2.4,1.25) 24(2.4,1.75)
  rrect40% 0.25x0.6 smd paste+0 mask+0: 9(-1.75,-2.4) 10(-1.25,-2.4) 11(-0.75,-2.4) 12(-0.25,-2.4) 13(0.25,-2.4) 14(0.75,-2.4) 15(1.25,-2.4) 16(1.75,-2.4) 25(1.75,2.4) 26(1.25,2.4) 27(0.75,2.4) 28(0.25,2.4) 29(-0.25,2.4) 30(-0.75,2.4) 31(-1.25,2.4) 32(-1.75,2.4)
  rrect3% 3.45x3.45 smd paste-1000 mask+0: 33(0,0)
  silkscreen extent -3.4,-2.55 2.55,2.55, body extent -2.8,-2.8 2.8,2.8, height 0.25
Samtec_FTSH-105-01-x-DV-K [mm] "Header(Shrouded), 1.27mm, 5x2, SMT"
  rect 2.79x0.74 smd: 1(-2.035,2.54) 2(2.035,2.54) 3(-2.035,1.27) 4(2.035,1.27) 5(-2.035,0) 6(2.035,0) 7(-2.035,-1.27) 8(2.035,-1.27) 9(-2.035,-2.54) 10(2.035,-2.54)
  silkscreen extent -3.73,-3.48 3.73,3.48, body extent -2.92,-3.18 2.92,3.17, height 6.13
Samtec_TSW-110-08-x-S [mm] "Header, 2.54mm, 10x1, TH"
  rrect50% 1.55x1.55 hole 1.02: 1(-11.43,0)
  round 1.55 hole 1.02: 2(-8.89,0) 3(-6.35,0) 4(-3.81,0) 5(-1.27,0) 6(1.27,0) 7(3.81,0) 8(6.35,0) 9(8.89,0) 10(11.43,0)
  silkscreen extent -12.7,-1.27 12.83,1.7, body extent -12.7,-1.27 12.83,1.27, height 8.38
SNT-100-BK-G [mil] "Samtec STEP model"
  round 1 on Mech3: 0(0,0)
  body extent -100,-50 100,50, height 344
SW_EVQ-21x05 [mm] "Panasonic"
  round 1.6 hole 1: 1(-2.5,0) 2(2.5,0)
  silkscreen extent -3.2,-3.2 3.2,3.2, body extent -3.15,-3.15 3.15,3.15, height 5.2
WEEE_Minimum [mil] "WEEElie bin"
  silkscreen extent -95,-172 99,104
WURTH_61300211121 [mm] "Header, 2.54mm, 2x1, TH"
  rrect50% 1.65x1.65 hole 1.15: 1(-1.27,0)
  round 1.65 hole 1.15: 2(1.27,0)
  body extent -2.54,-1.27 2.54,1.27, height 8.54
WURTH_61300311121 [mm] "Header, 2.54mm, 3x1, TH"
  rect 1.65x1.65 hole 1.15: 1(-2.54,0)
  round 1.65 hole 1.15: 2(0,0) 3(2.54,0)
  silkscreen extent -3.81,-1.27 3.81,1.6, body extent -3.81,-1.27 3.81,1.27, height 8.54
Wurth_691101710002 [mm] "Terminal Block, 5 mm, 2x1, TH"
  rect 1.8x1.8 hole 1.3: 1(-2.5,0)
  round 1.8 hole 1.3: 2(2.5,0)
  silkscreen extent -5,-4.5 5.6,5, body extent -5.6,-4 5.6,5, height 12.5

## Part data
"2.5V REF" 3.3V VIN: library part CMP-0055137-1, "Test Point, Miniature, Red, TH", Color=Red, Manufacturer=Keystone, Supplier Part Number 1=36-5000-ND
C1 C2 C3 C11 C12: library part CMP-0098153-1, "Chip Multilayer Ceramic Capacitors for General Purpose, 0603, 4.7uF, X5R, 15%, 10%, 16V", Manufacturer=Murata, Operating Temperature Range="-55°C to +85°C", TempCo=15%, Temperature Characteristic=X5R, Tolerance_%=10%, ValueDisplayed=4.7uF
C4: library part CMP-0007177-4, "CAP, CERM, 1100 pF, 50 V, +/- 5%, C0G/NP0, 0603", Cap_Case=0603, Manufacturer=MuRata, Supplier Part Number 1=490-1452-1-ND, TempCo=C0G/NP0, Tolerance_%=5%, Value1=Unknown, Value2=50V, ValueDisplayed=1100pF
C5: library part CMP-0086249-1, "CAP, CERM, 1 µF, 50 V,+/- 10%, X7R, AEC-Q200 Grade 1, 0805", Cap_Case=0805, Manufacturer=MuRata, TempCo=X7R, Tolerance_%=10%, Value2=50V, ValueDisplayed=1µF
C6: library part CMP-0007318-3, "CAP, CERM, 10 uF, 10 V, +/- 20%, X5R, 0603", Cap_Case=0603, Manufacturer=MuRata, TempCo=X5R, Tolerance_%=20%, Value1=Unknown, Value2=10V, ValueDisplayed=10uF
C7 C13 C15 C16: library part CMP-0095279-1, "Chip Multilayer Ceramic Capacitors for General Purpose, 0402, 0.10uF, X7R, 15%, 10%, 25V", Manufacturer=Murata, Operating Temperature Range="-55°C to +125°C", TempCo=15%, Temperature Characteristic=X7R, Tolerance_%=10%, ValueDisplayed=0.10uF
C8: library part CMP-0006525-2, "CAP, CERM, 0.47 uF, 6.3 V, +/- 10%, X6S, 0402", Cap_Case=0402, Manufacturer=MuRata, Supplier Part Number 1=GRM155C80J474KE19D-ND, TempCo=X6S, Tolerance_%=10%, Value1=Unknown, Value2=6.3V, ValueDisplayed=0.47uF
C9 C10: library part CMP-0095670-2, "Cap Ceramic 0.1uF 25V X7R 10% Pad SMD 0603 Soft Termination +125°C Automotive T/R", Manufacturer=Murata, Operating Temperature Range="-55°C to +125°C", TempCo=15%, Temperature Characteristic=X7R, Tolerance_%=10%, ValueDisplayed=0.1uF
C14: library part CMP-0081159-1, "CAP, CERM, 22 µF, 16 V,+/- 20%, X5R, 0603", Cap_Case=0603, Manufacturer=Samsung, Supplier Part Number 1=1276-7076-1-ND, TempCo=X5R, Tolerance_%=20%, Value2=16V, ValueDisplayed=22µF
C17 C18: library part CMP-0120248-1, "Ceramic Capacitor for Automotive 100pF  ±5% 100VDC C0G 0603 Paper T/R", Manufacturer=Murata, Operating Temperature Range="-55°C to +125°C", TempCo=30ppm/°C, Temperature Characteristic=C0G, Tolerance_%=5%, ValueDisplayed=100pF
FID1 FID2 FID3: library part CMP-0077181-1, "Fiducial mark.  There is nothing to buy or mount.", Manufacturer=N/A
GND GND: library part CMP-0055138-1, "Test Point, Miniature, Black, TH", Color=Black, Manufacturer=Keystone, Supplier Part Number 1=36-5001-ND
H1 H2 H3 H4: library part CMP-0003617-1, "Machine Screw, Round, #4-40 x 1/4, Nylon, Philips panhead", Manufacturer="B&F Fastener Supply", Supplier Part Number 1=H542-ND
H5 H6 H7 H8: library part CMP-0003610-1, "Standoff, Hex, 0.5\"L #4-40 Nylon", Manufacturer=Keystone, Supplier Part Number 1=36-1902C-ND
J1: "Terminal Block, 5 mm, 2x1, Tin, TH", Manufacturer="Wurth Elektronik", PartNumber="691 101 710 002", Supplier Part Number 1=732-2026-ND
J2: library part CMP-0075634-2, "Header(Shrouded), 1.27mm, 5x2, Gold, SMT", Color=Black, Current_A=3.3A, Manufacturer=Samtec, Supplier Part Number 1=SAM8799-ND
J3: library part CMP-0055334-1, "Header, 2.54mm, 6x1, Gold, R/A, TH", Color=Black, Current_A=3A, Manufacturer=Molex, Supplier Part Number 1=WM8112-ND, Voltage_V=350V
J4: library part CMP-0054794-2, "Header, 2.54 mm, 2x1, Gold, TH", Color=Black, Manufacturer="Wurth Elektronik", Supplier Part Number 1=732-5315-ND
J5 J6 J8 J10: library part CMP-0054796-1, "Header, 2.54 mm, 3x1, Gold, TH", Manufacturer="Wurth Elektronik", Supplier Part Number 1=732-5316-ND
J7: library part CMP-0055600-1, "Header, 2.54mm, 10x1, Gold, TH", Color=Black, Current_A=6.3A, Manufacturer=Samtec, Supplier Part Number 1=SAM1038-10-ND, Voltage_V=550V
J9: library part CMP-0075150-1, "Header, 2mm, 4x1, Gold, Black, R/A, SMT", Color=Black, Manufacturer=Harwin, Supplier Part Number 1=M22-5330405-ND
Logo3: library part CMP-0074847-1, "FCC_disclaimer"
Logo4: library part CMP-0074769-1
Oscillations Pressure: library part CMP-0055154-1, "Test Point, Miniature, Blue, TH", Color=Blue, Manufacturer=Keystone, Supplier Part Number 1=36-5117-ND
R1 R5: library part CMP-0025767-3, "RES, 27, 5%, 0.1 W, 0603", Manufacturer=Vishay-Dale, Power_W=100mW, Supplier Part Number 1=541-27GCT-ND, TempCo="200 ppm/C", Tolerance_%=5%, Value2=0.1W, Value_Code=27R0, ValueDisplayed=27
R2: library part CMP-0022438-4, "RES, 47.0 k, 1%, 0.1 W, AEC-Q200 Grade 0, 0603", Manufacturer=Vishay-Dale, Power_W=100mW, Supplier Part Number 1=541-47.0KHCT-ND, TempCo="100 ppm/C", Tolerance_%=1%, Value2=0.1W, Value_Code=47k0, ValueDisplayed=47.0k
R3: library part CMP-0120247-1, "RES Thick Film, 330Ω, 1%, 0.1W, 100ppm/°C, 0603", Approved Alternate Part Number=541-1.00HHCT-ND, Manufacturer=Vishay, Operating Temperature Range="-55°C to +155°C", Power=100mW, TempCo=100ppm/°C, Tolerance_%=1%, Voltage=75V
R4 R6 R7 R8: library part CMP-0021998-4, "RES, 10.0 k, 1%, 0.1 W, AEC-Q200 Grade 0, 0603", Manufacturer=Vishay-Dale, Power_W=100mW, Supplier Part Number 1=541-10.0KHCT-ND, TempCo="100 ppm/C", Tolerance_%=1%, Value2=0.1W, Value_Code=10k0, ValueDisplayed=10.0k
R9 R10: library part CMP-0120246-1, "RES Thick Film, 270kΩ, 1%, 0.1W, 100ppm/°C, 0603", Approved Alternate Part Number=541-1.00HHCT-ND, Manufacturer=Vishay, Operating Temperature Range="-55°C to +155°C", Power=100mW, TempCo=100ppm/°C, Tolerance_%=1%, Voltage=75V
R11 R13 R14 R16 R17: library part CMP-0022204-4, "RES, 20.0 k, 1%, 0.1 W, AEC-Q200 Grade 0, 0603", Manufacturer=Vishay-Dale, Power_W=100mW, Supplier Part Number 1=541-20.0KHCT-ND, TempCo="100 ppm/C", Tolerance_%=1%, Value2=0.1W, Value_Code=20k0, ValueDisplayed=20.0k
R12 R15: library part CMP-0082532-1, "RES, 499, 1%, 0.1 W, 0603", Manufacturer=Vishay-Dale, Power_W=100mW, Supplier Part Number 1=541-3986-1-ND, TempCo="100 ppm/C", Tolerance_%=1%, Value2=0.1W, Value_Code=499R, ValueDisplayed=499
R18: library part CMP-0022430-4, "RES, 45.3 k, 1%, 0.1 W, AEC-Q200 Grade 0, 0603", Manufacturer=Vishay-Dale, Power_W=100mW, Supplier Part Number 1=541-45.3KHCT-ND, TempCo="100 ppm/C", Tolerance_%=1%, Value2=0.1W, Value_Code=45k3, ValueDisplayed=45.3k
R19 R20: library part CMP-0022201-5, "RES, 200, 1%, 0.1 W, AEC-Q200 Grade 0, 0603", Manufacturer=Vishay-Dale, Power_W=100mW, Supplier Part Number 1=541-200HCT-ND, TempCo="100 ppm/C", Tolerance_%=1%, Value2=0.1W, Value_Code=200R, ValueDisplayed=200
R21: library part CMP-0082533-1, "RES, 4.99 k, 1%, 0.1 W, 0603", Manufacturer=Vishay-Dale, Power_W=100mW, Supplier Part Number 1=541-3985-1-ND, TempCo="100 ppm/C", Tolerance_%=1%, Value2=0.1W, Value_Code=4k99, ValueDisplayed=4.99k
R22: library part CMP-0024072-3, "RES, 2.49 k, 0.1%, 0.1 W, 0603", Manufacturer="Yageo America", Power_W=100mW, TempCo="25 ppm/C", Tolerance_%=0.1%, Value2=0.1W, Value_Code=2k49, ValueDisplayed=2.49k
R23: library part CMP-0095689-1, "Jumper 0.063W, 1/16W Chip Resistor 0402 (1005 Metric) Moisture Resistant Thick Film", Digikey Part Number=311-0.0LRCT-ND, Manufacturer=Yageo, Mouser Part Number=603-RC0402FR-070RL, Operating Temperature Range="-55°C to +155°C", Power_W=63mW
S1: library part CMP-0002172-2, "Switch, Tactile, SPST-NO, 0.02A, 15V, TH", CurrentRating_mA=20A, Manufacturer=Panasonic, Supplier Part Number 1=P12225SCT-ND
SH-J1 SH-J2 SH-J3 SH-J4 SH-J5: library part CMP-0003623-3, "Shunt, 100mil, Gold plated, Black", Alternate Manufacturer=3M, Alternate PartNumber=969102-0000-DA, Manufacturer=Samtec, PartNumber=SNT-100-BK-G, Supplier Part Number 1=SAM8858-ND
U1: library part CMP-0120272-1, "200-mA, 18-V, ultra-low-IQ, low-dropout (LDO) voltage regulator with enable 5-SOT-23 -40 to 125", Digikey Part Number=296-TPS7A2433DBVRCT-ND, Dropout Voltage=160mV, Manufacturer="Texas Instruments", Max Supply Voltage=18V, Min Supply Voltage=3.8V, Mouser Part Number=595-TPS7A2433DBVR, Nominal Supply Current=2-15uA, Operating Temperature Range="-40°C to +125°C", Output Voltage=3.3V
U2: library part CMP-0120268-2, "Quad, 5.5-V, 1-MHz, 4-mV offset voltage, RRO operational amplifier 14-TSSOP -40 to 125", Digikey Part Number=296-51366-1-ND, Input Bias Current=0.00001uA, Input Offset Voltage=1mV, Manufacturer="Texas Instruments", Max Dual Supply Voltage=2.75V, Max Supply Voltage=5.5V, Min Dual Supply Voltage=1.25V, Min Supply Voltage=2.5V, Mouser Part Number=595-LMV324AIPWR, Nominal Supply Current=70uA, Operating Temperature Range="-40°C to +125°C", Output Current Per Channel=40mA, Voltage Gain=98dB
U3: library part CMP-0084732-1, "High Bandwidth Low-Iq Programmable Shunt Regulator, DBZ0003A (SOT-23-3)", Alternate Manufacturer="Texas Instruments"
U4: library part CMP-0093968-1, "MSPM0L130x Mixed-Signal Microcontrollers", Frequency_Fixed=32MHz, Manufacturer="Texas Instruments", Max Supply Voltage=3.6V, Min Supply Voltage=1.62V, Operating Temperature Range="-40°C to +125°C"
U5: library part CMP-0120266-1, "Cost and Size Optimized, Low Power, 1.8-V to 5.5-V Selectable Gain Instrumentation Amplifier", Digikey Part Number=296-INA350ABSIDSGRCT-ND, Input Bias Current=0.00000065uA, Input Offset Voltage=0.2mV, Manufacturer="Texas Instruments", Max Dual Supply Voltage=2.75V, Max Supply Voltage=5.5V, Min Dual Supply Voltage=900mV, Min Supply Voltage=1.8V, Mouser Part Number=595-INA350CDSIDSGR, Nominal Supply Current=100uA, Operating Temperature Range="-40°C to +125°C", Output Current Per Channel=20mA, Voltage Gain=0.001V/mV
U6: library part CMP-0090268-2, "11V, 1A H-bridge motor driver, PWM, PH/EN, ½ bridge control, with low power sleep mode", Manufacturer="Texas Instruments", Max Supply Voltage=11V, Min Supply Voltage=1.65V, Operating Temperature Range="-40°C to +150°C", Part Number=DRV8210DSG, Switching Frequency=100kHz
U7: library part CMP-0120245-1, "Pressure Sensor ±7.25PSI (±50kPa) Compound Male - 0.1\" (2.59mm) Tube -43 mV ~ 42 mV 6-SMD Module", Digikey Part Number=Z3639-ND, Manufacturer="Omron Electronics Inc-EMC Div", Mouser Part Number=653-2SMPP-03, Operating Supply Current=100uA, Operating Temperature Range="-10°C to +100°C"
ZZ1: library part CMP-0003616-3
ZZ2: library part CMP-0077236-1
ZZ3: library part CMP-0077237-1
ZZ4: library part CMP-0077238-1

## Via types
v1: diameter 20, hole 10, Top Layer to Bottom Layer, tented both sides, 148 vias
v2: diameter 19.68, hole 10, Top Layer to Bottom Layer, 7 vias
v3: diameter 19.68, hole 7.87, Top Layer to Bottom Layer, tented both sides, 2 vias
v4: diameter 24, hole 8, Top Layer to Bottom Layer, tented both sides, 1 vias
v5: diameter 24, hole 10, Top Layer to Bottom Layer, tented both sides, 1 vias

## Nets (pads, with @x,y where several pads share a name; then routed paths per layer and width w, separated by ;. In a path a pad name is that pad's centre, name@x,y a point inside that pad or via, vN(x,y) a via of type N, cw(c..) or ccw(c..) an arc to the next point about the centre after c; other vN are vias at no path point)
"1.25V REF": R14.1 U2.1 U2.2 U2.5 U2.10 U5.5 | length 1478.6
  Top Layer w10: R14.1@1029.89,1480.39 1029.89,1481.38 1124.09,1575.57 1124.09,1758.4 1278.52,1912.84 1311.84,1912.84 1313.31,1914.32 1376.55,1914.32 ; U2.1@1313.31,2016.68 1313.31,1991.09 1314.79,1989.61 1359.23,1989.61 1376.55,1972.29 1376.55,1914.32 ; U5.5@1960.3,1772.72 1960.3,1853.82 1899.81,1914.32 1545.6,1914.32 1376.55,1914.32
2.5V_REF: "2.5V REF.1" C2.2 C3.2 R3.1 R4.2 R18.2 U3.1 U3.2 U4.27 | length 2076.9
  Top Layer w10: v1(975.45,1773) 975.45,1779.27 1047.16,1850.98 R4.2@1047.16,1851.96 ; U3.2@1038.96,2168.11 1045.77,2161.3 U3.2@1050.25,2161.3 ; C3.2@1047.16,1940.26 C3.2@1053.15,1946.25 ; C2.2@1050.25,2014.42 C2.2@1053.15,2011.52 ; v1(1065.86,1113.9) 1065.86,1113.6 1154.6,1024.87 1248.7,1024.87 1390.56,883.01 U4.27@1415.61,883.01 ; R18.2@1181.82,2249.41 R18.2@1183.85,2247.38 R18.2@1190.4,2253.94
  Top Layer w15: U3.2@1038.96,2168.11 1038.96,2249.41 R18.2@1181.82,2249.41 ; R4.2@1047.16,1851.96 C3.2@1047.16,1940.26 ; C2.2@1050.25,2014.42 U3.1@1050.25,2086.49 U3.2@1050.25,2161.3 ; C3.2@1053.15,1946.25 C2.2@1053.15,2011.52 ; R18.2@1190.4,2253.94 1190.4,2408.56
  Bottom Layer w10: v1(975.45,1773) 924.26,1721.81 924.26,1143.38 953.74,1113.9 v1(1065.86,1113.9)
3.3V: 3.3V.1 C1.2 C6.1 C7.2 C13.2 C16.2 J2.1 J10.3 R2.2 R3.2 R7.2 R8.2 U1.5 U2.4 U4.4 U5.7 U6.8 | length 8680.2
  Top Layer w10: C1.2@755.74,2236.51 766.37,2247.13 C1.2@766.49,2247.26 ; R3.2@973.82,2247.26 975.97,2249.41 R3.2@976.76,2250.2 ; U6.8@1079.83,655.57 1079.83,710.94 1087.01,718.12 1090.95,718.12 ; v5(1208.2,1893.55) 1211.99,1893.55 1217.56,1899.12 1229.08,1899.12 1269.87,1939.91 U2.4@1313.31,1939.91 ; R8.2@1240.35,459.7 v1(1294.45,459.7) 1350.52,459.7 R7.2@1353.89,463.07 ; v1(1433.05,599.3) C6.1@1484.54,599.3 1484.54,663.25 1490.33,669.03 1493.45,669.03 1500.26,675.85 U4.4@1500.26,758.99 ; v1(1663.72,1858.31) 1723.77,1798.27 1750.51,1798.27 1907.69,1798.27 1920.85,1785.11 1920.85,1772.8 U5.7@1920.93,1772.72 ; R2.2@2336.45,1636.93 2527.4,1636.93 2606,1558.33 v1(2606,1320)
  Top Layer w15: U1.5@766.37,2183.44 C1.2@766.37,2247.13 ; R3.2@976.76,2250.2 3.3V.1@976.76,2400.4 ; 1090.95,718.12 1092.41,716.67 1115.84,716.67 1189.49,643.02 1189.49,518.92 1150.36,479.78 v1(1150.36,459.7)
  Top Layer w20: v1(711.67,2231.83) 715.46,2231.83 729.02,2245.39 C1.2@753.77,2245.39 ; C1.2@766.49,2247.26 R3.2@973.82,2247.26
  Top Layer w30: J2.1@2435.24,1345.46 2580.54,1345.46 v1(2606,1320)
  Bottom Layer w10: J10.3@2143.79,1883.24 2185.72,1841.31 2323.02,1841.31 2606,1558.33 v1(2606,1320)
  Bottom Layer w15: 711.98,1850.36 1009.29,1850.36 ; 1009.41,1850.73 1036.02,1893.55 v5(1208.2,1893.55) 1628.49,1893.55 v1(1663.72,1858.31)
  Bottom Layer w45: v1(711.67,2231.83) 711.67,754.29 1006.26,459.7 v1(1150.36,459.7) v1(1294.45,459.7) 1390.68,459.7 ; v1(1433.05,599.3) 1433.05,502.07 1390.68,459.7 ; v1(2606,1320) 2676,1250 2676,669 2592.45,585.45 2406.02,585.45 2280.28,459.7 1390.68,459.7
